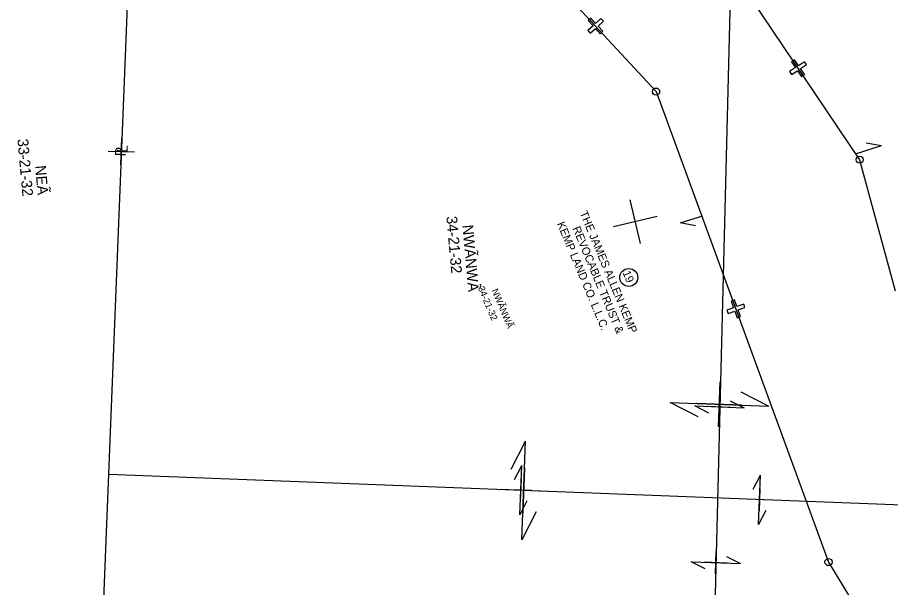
# Model space of a CAD drawing. Extents: x 2814293 to 2835768, y 121185 to 156337.
# Drawn here: x 2820173 to 2822119, y 124221 to 125490 of the extents above; entities that cross this region are included whole.
import ezdxf

# ---------------------------------------------------------------- set-up
doc = ezdxf.new("R2010")
doc.units = 0
for name, color, linetype in [('Default', 7, 'Continuous'), ('Photo-Retaining wall', 7, 'Continuous'), ('Roadway-Alignment notes', 7, 'Continuous'), ('Roadway-Ditches', 7, 'Continuous'), ('Roadway-Edge of pavement', 7, 'Continuous'), ('Roadway-Edge of shoulder', 7, 'Continuous'), ('Roadway-Entrances', 7, 'Continuous'), ('Roadway-New rw', 7, 'Continuous'), ('Scratch-2', 7, 'Continuous'), ('Text-New rw label', 7, 'Continuous')]:
    doc.layers.add(name, color=color, linetype=linetype)

msp = doc.modelspace()

# ---------------------------------------------------------------- linework, layer by layer
at = {"layer": 'Default'}
for p, q in [((2821561.8, 124986.8), (2821539, 125084.2)), ((2821599.1, 125046.9), (2821501.7, 125024))]:
    msp.add_line(p, q, dxfattribs=at)
at = {"layer": 'Roadway-Ditches'}
msp.add_circle((2821535.8, 124911.2), 20, dxfattribs=at)
at = {"layer": 'Roadway-Edge of pavement'}
for p, q in [((2821736.7, 124597.8), (2821738.7, 124647.8)), ((2821761.5, 124636.7), (2821792.7, 124620.7)), ((2821682.7, 124624.9), (2821792.7, 124620.7)), ((2821713.9, 124608.9), (2821682.7, 124624.9)), ((2821762.7, 124621.8), (2821712.7, 124623.8)), ((2821737.7, 124622.8), (2821737.7, 124622.8)), ((2821281.2, 124461.3), (2821297.2, 124492.4)), ((2821292.9, 124382.5), (2821297.2, 124492.4)), ((2821296, 124462.5), (2821294.1, 124412.5)), ((2821813.3, 124439.9), (2821829.3, 124471.1)), ((2821825, 124361.1), (2821829.3, 124471.1)), ((2821320, 124436.5), (2821270, 124438.5)), ((2821295, 124437.5), (2821295, 124437.5)), ((2821828.1, 124441.1), (2821826.2, 124391.1)), ((2821852.1, 124415.1), (2821802.2, 124417.1)), ((2821308.9, 124413.7), (2821292.9, 124382.5)), ((2821827.2, 124416.1), (2821827.2, 124416.1)), ((2821841, 124392.3), (2821825, 124361.1)), ((2821729, 124250.9), (2821730.9, 124300.9)), ((2821753.8, 124289.8), (2821784.9, 124273.8)), ((2821675, 124278), (2821784.9, 124273.8)), ((2821706.1, 124262), (2821675, 124278)), ((2821754.9, 124274.9), (2821704.9, 124276.9)), ((2821729.9, 124275.9), (2821729.9, 124275.9))]:
    msp.add_line(p, q, dxfattribs=at)
at = {"layer": 'Roadway-Edge of shoulder'}
for p, q in [((2820403.8, 125162.4), (2820405.9, 125221.3)), ((2820375.4, 125192.9), (2820434.3, 125190.8))]:
    msp.add_line(p, q, dxfattribs=at)
at = {"layer": 'Roadway-Entrances'}
for p, q in [((2820428.2, 125785.8), (2820323.2, 123130.1)), ((2821766.3, 125728.5), (2821700.5, 123062.8)), ((2822041.3, 125187), (2822099.1, 125205.2)), ((2822064.6, 125211.4), (2822099.1, 125205.2)), ((2821652.4, 125033.5), (2821698.3, 125048)), ((2821684.6, 125026.6), (2821650.2, 125032.8)), ((2820377.3, 124472.9), (2825726, 124265.6))]:
    msp.add_line(p, q, dxfattribs=at)
at = {"layer": 'Roadway-New rw'}
for p, q in [((2821349, 125593.1), (2821596.6, 125325.2)), ((2821794.9, 125552.8), (2822050.4, 125173.6)), ((2821596.6, 125325.2), (2821981.1, 124277.3)), ((2822050.4, 125173.6), (2822129.4, 124881.4)), ((2821981.1, 124277.3), (2822086, 124104.4))]:
    msp.add_line(p, q, dxfattribs=at)
for points in [[(2821444.3, 125461.1), (2821449.7, 125455.2), (2821461.5, 125466), (2821472.3, 125454.2), (2821478.2, 125459.6), (2821467.4, 125471.4), (2821479.2, 125482.2), (2821473.8, 125488.1), (2821462, 125477.3), (2821451.2, 125489.1), (2821445.3, 125483.7), (2821456.1, 125471.9), (2821444.3, 125461.1)], [(2821894.1, 125369.7), (2821898.5, 125363), (2821911.8, 125371.9), (2821920.7, 125358.6), (2821927.4, 125363.1), (2821918.5, 125376.4), (2821931.8, 125385.3), (2821927.3, 125391.9), (2821914, 125383), (2821905.1, 125396.3), (2821898.5, 125391.9), (2821907.4, 125378.6), (2821894.1, 125369.7)], [(2821754.3, 124838.2), (2821757.1, 124830.7), (2821772.1, 124836.2), (2821777.6, 124821.2), (2821785.1, 124823.9), (2821779.6, 124838.9), (2821794.6, 124844.4), (2821791.9, 124852), (2821776.9, 124846.5), (2821771.4, 124861.5), (2821763.8, 124858.7), (2821769.3, 124843.7), (2821754.3, 124838.2)]]:
    msp.add_lwpolyline(points, close=True, dxfattribs=at)
at = {"layer": 'Scratch-2'}
for p, q in [((2821550.4, 125035.5), (2821550.4, 125035.5)), ((2821735.8, 124578.7), (2821739.7, 124678.7)), ((2821785.4, 124656.4), (2821847.7, 124624.4)), ((2821627.8, 124632.9), (2821847.7, 124624.4)), ((2821690.1, 124600.9), (2821627.8, 124632.9)), ((2821787.7, 124626.7), (2821687.8, 124630.6)), ((2821737.8, 124628.7), (2821737.8, 124628.7)), ((2821273.9, 124484.4), (2821305.9, 124546.6)), ((2821297.4, 124326.8), (2821305.9, 124546.6)), ((2821303.6, 124486.7), (2821299.7, 124386.7)), ((2821351.6, 124434.8), (2821251.7, 124438.6)), ((2821301.7, 124436.7), (2821301.7, 124436.7)), ((2821329.4, 124389), (2821297.4, 124326.8))]:
    msp.add_line(p, q, dxfattribs=at)
at = {"layer": 'Text-New rw label'}
for centre in [(2821596.6, 125325.2), (2822050.4, 125173.6), (2821981.1, 124277.3)]:
    msp.add_circle(centre, 8, dxfattribs=at)

# ---------------------------------------------------------------- texts
at = {"layer": 'Photo-Retaining wall'}
for s, p in [('34-21-32', (2821199.4, 124887.7)), ('NWÃNWÃ', (2821229.8, 124882.5))]:
    msp.add_text(s, height=15, rotation=292.7163, dxfattribs=at).set_placement(p)
at = {"layer": 'Roadway-Alignment notes'}
for s, p in [('33-21-32', (2820173.2, 125219.2)), ('NEÃ', (2820212.6, 125159.9)), ('34-21-32', (2821129.1, 125046.9)), ('NWÃNWÃ', (2821164.9, 125027.6))]:
    msp.add_text(s, height=24, rotation=275.0693, dxfattribs=at).set_placement(p)
at = {"layer": 'Roadway-Ditches'}
for s, p in [('THE JAMES ALLEN KEMP', (2821426, 125055.1)), ('KEMP LAND CO. L.L.C.', (2821375.3, 125031)), ('REVOCABLE TRUST &', (2821410, 125020.7)), ('19', (2821521.5, 124922.2))]:
    msp.add_text(s, height=18, rotation=292.7163, dxfattribs=at).set_placement(p)
at = {"layer": 'Roadway-Edge of shoulder'}
for s, p in [('P', (2820414.1, 125180.8)), ('L', (2820418.7, 125188.6))]:
    msp.add_text(s, height=23.6, rotation=87.9775, dxfattribs=at).set_placement(p)

doc.saveas('drawing.dxf')
